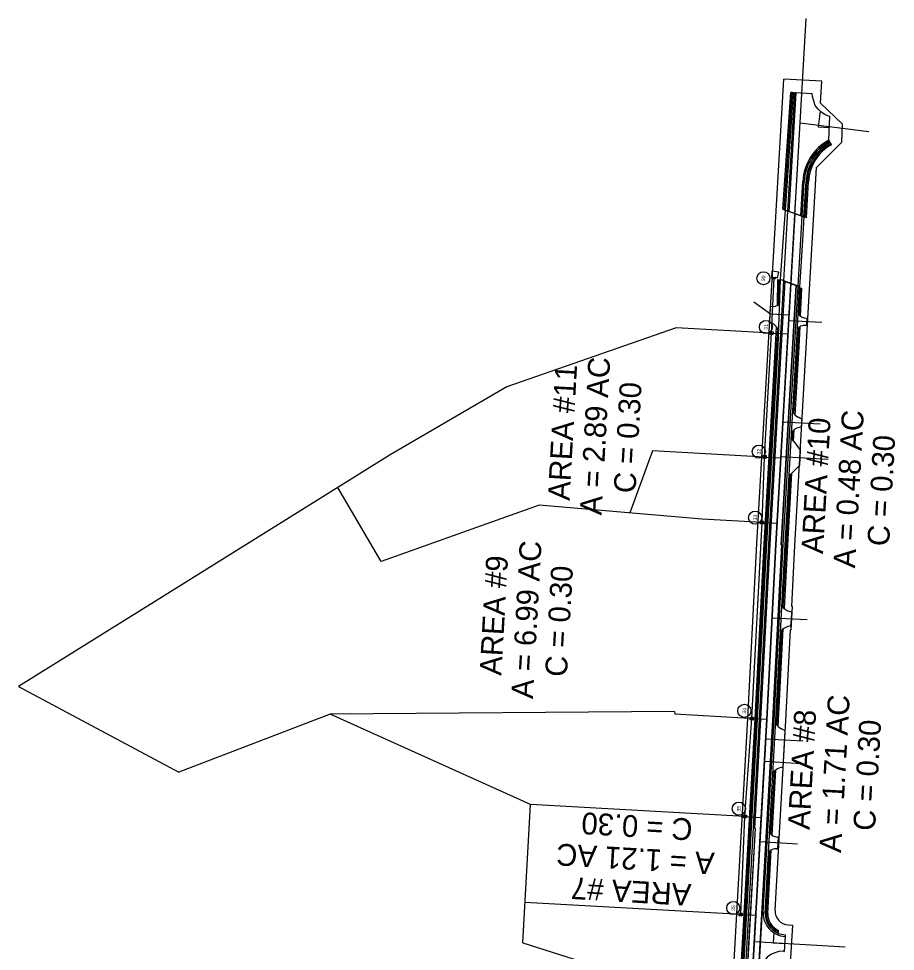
# Model space of a CAD drawing. Extents: x 1972588 to 1974207, y 734965 to 738282.
# Drawn here: x 1972868 to 1974207, y 736857 to 738282 of the extents above; entities that cross this region are included whole.
import ezdxf

# ---------------------------------------------------------------- set-up
doc = ezdxf.new("R2010")
doc.units = 0
for name, color, linetype in [('_CIVIL_CONSTRUCTION', 7, 'Continuous'), ('BR_P_Gen_Ground_Slope', 7, 'Continuous'), ('BR_X_Beam Seat', 7, 'Continuous'), ('BR_X_Bottom of Beam', 7, 'Continuous'), ('BR_X_Gen_Approach_Slab', 7, 'Continuous'), ('BR_X_Pier', 7, 'Continuous'), ('DR_P_GenericNode', 7, 'Continuous'), ('DR_P_Headwall', 7, 'Continuous'), ('DR_P_Storm_Sewer', 7, 'Continuous'), ('DR_X_Cells', 7, 'Continuous'), ('DR_X_GenericNode', 7, 'Continuous'), ('DR_X_Storm_Sewer', 7, 'Continuous'), ('DT_X_Contour_Major', 7, 'Continuous'), ('GE_P_Alignment', 7, 'Continuous'), ('GE_X_Alignment_1000_Cardinal_Points', 7, 'Continuous'), ('GK_Drainage_Nodes', 7, 'Continuous'), ('PF_P_Grade_Line', 7, 'Continuous'), ('RS_Raster1', 7, 'Continuous'), ('SC_ProfileRun2', 7, 'Continuous'), ('SC_ProfileRun4', 7, 'Continuous'), ('SC_Scratch1', 7, 'Continuous')]:
    doc.layers.add(name, color=color, linetype=linetype)

msp = doc.modelspace()

# ---------------------------------------------------------------- linework, layer by layer
at = {"layer": '_CIVIL_CONSTRUCTION'}
for p, q in [((1974014.8, 737818.6), (1974016.3, 737842.9)), ((1974014.8, 737818.6), (1974019.2, 737816)), ((1974071, 737824.5), (1974072.3, 737824.5)), ((1974071.6, 737813.2), (1974072.3, 737824.5)), ((1974071.6, 737813.2), (1974069.3, 737813.3)), ((1974064.2, 737669.6), (1974058.1, 737672.9)), ((1974063.5, 737658.5), (1974059.6, 737657.5)), ((1974063.5, 737658.5), (1974064.2, 737669.6)), ((1974047.7, 737640.6), (1974053.5, 737633.2)), ((1974053.5, 737633.2), (1974061.5, 737622.9)), ((1974061.5, 737622.9), (1974060.3, 737599.1)), ((1974050.7, 737589.6), (1974044.4, 737583.7)), ((1974060.3, 737599.1), (1974050.7, 737589.6)), ((1974048.7, 737374.9), (1974045.1, 737376.1)), ((1974048.2, 737364.6), (1974048.7, 737374.9)), ((1974047.2, 737353.7), (1974048.2, 737364.6)), ((1974038.5, 737194), (1974032.9, 737196.8)), ((1974035.4, 737137.9), (1974038.5, 737194)), ((1974028.4, 737031.3), (1974026, 737031.5)), ((1974027.4, 737013.6), (1974028.4, 737031.3)), ((1974025.5, 737013.7), (1974027.4, 737013.6))]:
    msp.add_line(p, q, dxfattribs=at)
for centre, radius, start, end in [((1974020.1, 737857.4), 15, 255.1663, 311.8101), ((1974071.1, 737839.5), 15, 210.5665, 269.302), ((1974006.4, 737794.5), 25, 27.4365, 59.4001), ((1974068.8, 737798.3), 15, 87.9927, 141.3926), ((1974067.6, 737690.5), 20, 208.4916, 241.7135), ((1974064.6, 737638.1), 20, 104.3781, 144.9149), ((1974051, 737395.2), 20, 208.814, 252.6777), ((1974047.8, 737333.7), 20, 91.8272, 145.2374), ((1974041.6, 737214.8), 20, 208.696, 244.1609), ((1974036.2, 737118), 20, 92.4278, 145.0009), ((1974027.2, 737046.5), 15, 213.6591, 265.4279), ((1974024.5, 736998.7), 15, 86.2628, 139.9193)]:
    msp.add_arc(centre, radius, start, end, dxfattribs=at)
at = {"layer": 'BR_P_Gen_Ground_Slope'}
msp.add_lwpolyline([(1974020.4, 737886.5), (1974020.3, 737884.5), (1974019.3, 737884.6), (1974019.4, 737886.6), (1974023.4, 737886.4), (1974023.3, 737884.4), (1974022.3, 737884.4), (1974022.4, 737886.4)], dxfattribs=at)
at = {"layer": 'BR_X_Beam Seat'}
for p, q in [((1973995.4, 737480.2), (1974036.2, 738189.8)), ((1974094.2, 738186.4), (1974036.2, 738189.8)), ((1974092.2, 738152.8), (1974094.2, 738186.4)), ((1974092.2, 738152.8), (1974126.1, 738121)), ((1974125.1, 738093.3), (1974126.1, 738121)), ((1974086.5, 738054.6), (1974125.1, 738093.3)), ((1974053.3, 737477), (1974086.5, 738054.6)), ((1973981.5, 737212.7), (1973995.4, 737480.2)), ((1974048.4, 737383.8), (1974053.3, 737477)), ((1974047.6, 737348.1), (1974049.4, 737383.8)), ((1974049.4, 737383.8), (1974048.4, 737383.8)), ((1974039.4, 737209.6), (1974046.6, 737348.2)), ((1974046.6, 737348.2), (1974047.6, 737348.1)), ((1973902.9, 735811.8), (1973981.5, 737212.7)), ((1974023.1, 736919.5), (1974039.4, 737209.6)), ((1974042.9, 736897.3), (1974049.4, 736896.9)), ((1974049.4, 736896.9), (1974046.1, 736839))]:
    msp.add_line(p, q, dxfattribs=at)
msp.add_arc((1974044.1, 736918.3), 21, 176.7892, 266.7317, dxfattribs=at)
at = {"layer": 'BR_X_Bottom of Beam'}
msp.add_lwpolyline([(1974023.4, 737886.4), (1974023.8, 737886.9), (1974026.6, 737886), (1974028.8, 737894.7), (1974021.8, 737895.7), (1974018.3, 737896.3), (1974017.8, 737886.7), (1974019.4, 737886.6)], close=True, dxfattribs=at)
at = {"layer": 'BR_X_Gen_Approach_Slab'}
msp.add_circle((1974017.7, 737801.6), 0.5, dxfattribs=at)
at = {"layer": 'BR_X_Pier'}
for p, q in [((1973872, 737809.8), (1973613.2, 737719.5)), ((1974017.7, 737801.6), (1973872, 737809.8)), ((1974017.7, 737801.6), (1974042.8, 737800.2)), ((1974031.9, 737610.8), (1974042.8, 737800.2)), ((1973613.2, 737719.5), (1973435.2, 737615.4)), ((1973435.2, 737615.4), (1973083.5, 737395.9)), ((1973835.8, 737621.8), (1973801.4, 737526.8)), ((1974007, 737612.2), (1973835.8, 737621.8)), ((1974007, 737612.2), (1974031.9, 737610.8)), ((1974026.2, 737511), (1974031.9, 737610.8)), ((1973421.6, 737452.5), (1973355.4, 737565.5)), ((1973662.7, 737538.8), (1973421.6, 737452.5)), ((1973911.8, 737517.3), (1973662.7, 737538.8)), ((1974003.2, 737512.3), (1973911.8, 737517.3)), ((1974003.2, 737512.3), (1974026.2, 737511)), ((1974010.4, 737211.3), (1974026.2, 737511)), ((1973083.5, 737395.9), (1972867.8, 737261.4)), ((1972867.8, 737261.4), (1973112.6, 737130.4)), ((1973343.5, 737219.4), (1973112.6, 737130.4)), ((1973869.3, 737223.5), (1973343.5, 737219.4)), ((1973649.5, 737081.4), (1973343.5, 737219.4)), ((1973869.3, 737223.5), (1973869.9, 737219.2)), ((1974010.4, 737211.3), (1973869.9, 737219.2)), ((1973987.5, 737212.6), (1973999.4, 737212)), ((1974002, 737061.6), (1974010.4, 737211.3)), ((1973637.6, 736869.7), (1973649.5, 737081.4)), ((1973977.1, 737063), (1973649.5, 737081.4)), ((1973977.1, 737063), (1974002, 737061.6)), ((1973993.6, 736911.9), (1974002, 737061.6)), ((1973970.7, 736913.1), (1973641.1, 736931.6)), ((1973970.7, 736913.1), (1973993.6, 736911.9)), ((1973993.6, 736911.9), (1973988.4, 736818.5)), ((1973637.6, 736869.7), (1973783.2, 736823.8))]:
    msp.add_line(p, q, dxfattribs=at)
for centre in [(1974005.2, 737885.3), (1974009, 737810.9), (1973998.3, 737620.4), (1973992.7, 737519.5), (1973976.1, 737224.3), (1973967.7, 737074.8), (1973959.2, 736923.1)]:
    msp.add_circle(centre, 10, dxfattribs=at)
at = {"layer": 'DR_P_GenericNode'}
for points in [[(1974015.4, 737799.6), (1974015.7, 737803.9), (1974020, 737803.7), (1974019.7, 737799.3)], [(1974016.1, 737800.2), (1974016.3, 737803.2), (1974019.3, 737803), (1974019.1, 737800)], [(1974016.5, 737800.5), (1974016.6, 737802.8), (1974018.9, 737802.7), (1974018.8, 737800.4)], [(1974004.7, 737610.2), (1974004.9, 737614.5), (1974009.3, 737614.3), (1974009, 737610)], [(1974005.4, 737610.8), (1974005.6, 737613.8), (1974008.6, 737613.7), (1974008.4, 737610.7)], [(1974005.8, 737611.2), (1974005.9, 737613.5), (1974008.2, 737613.3), (1974008, 737611)], [(1974000.9, 737510.3), (1974001.2, 737514.6), (1974005.5, 737514.3), (1974005.3, 737510)], [(1974001.6, 737510.9), (1974001.8, 737513.9), (1974004.8, 737513.7), (1974004.6, 737510.7)], [(1974002, 737511.2), (1974002.1, 737513.5), (1974004.4, 737513.4), (1974004.3, 737511.1)], [(1973985.2, 737210.5), (1973985.4, 737214.9), (1973989.7, 737214.6), (1973989.5, 737210.3)], [(1973985.9, 737211.2), (1973986, 737214.2), (1973989, 737214), (1973988.9, 737211)], [(1973986.3, 737211.5), (1973986.4, 737213.8), (1973988.7, 737213.7), (1973988.5, 737211.4)], [(1973974.8, 737061), (1973975, 737065.3), (1973979.4, 737065.1), (1973979.1, 737060.7)], [(1973975.5, 737061.6), (1973975.7, 737064.6), (1973978.6, 737064.4), (1973978.5, 737061.4)], [(1973975.9, 737061.9), (1973976, 737064.2), (1973978.3, 737064.1), (1973978.1, 737061.8)], [(1973968.4, 736911.1), (1973968.6, 736915.4), (1973972.9, 736915.2), (1973972.7, 736910.9)], [(1973969.1, 736911.7), (1973969.2, 736914.7), (1973972.2, 736914.6), (1973972.1, 736911.6)], [(1973969.5, 736912.1), (1973969.6, 736914.4), (1973971.9, 736914.2), (1973971.7, 736911.9)]]:
    msp.add_lwpolyline(points, close=True, dxfattribs=at)
at = {"layer": 'DR_P_Headwall'}
for p, q in [((1974016.1, 737830.5), (1973990.7, 737848.7)), ((1974044.5, 737828.9), (1974016.1, 737830.5)), ((1974094.4, 737817.7), (1974044, 737820.5)), ((1974091.8, 737662.5), (1974035.1, 737665.7)), ((1974104, 737608.6), (1974032, 737612.6)), ((1974072, 737363.2), (1974018.5, 737366.2)), ((1974065.4, 737178.1), (1974008.7, 737181.3)), ((1974063.5, 737143.6), (1974006.8, 737146.8)), ((1974057.4, 737020.7), (1973999.9, 737024))]:
    msp.add_line(p, q, dxfattribs=at)
at = {"layer": 'DR_P_Storm_Sewer'}
for p, q in [((1974038.8, 737989.2), (1974051.1, 738168.9)), ((1974051.1, 738168.9), (1974053.1, 738168.8)), ((1974107.1, 738093), (1974106.2, 738094.8)), ((1974067.2, 737979.2), (1974070.3, 738033.1)), ((1974038.8, 737989.2), (1974042.7, 737987.8)), ((1974067.2, 737979.2), (1974064.2, 737980.2)), ((1974027.8, 737782.2), (1974031.4, 737883.3)), ((1974036.5, 737881.4), (1974031.4, 737883.3)), ((1974055.7, 737780.6), (1974060.2, 737872.3)), ((1974060.2, 737872.3), (1974058.1, 737873.1)), ((1974010.3, 737479.4), (1974027.8, 737782.2)), ((1974038.3, 737477.8), (1974055.7, 737780.6)), ((1973996.4, 737211.9), (1974010.3, 737479.3)), ((1974024.4, 737210.4), (1974038.3, 737477.9)), ((1973918.6, 735825.1), (1973996.4, 737211.9)), ((1974007.8, 736914.5), (1974024.4, 737210.4))]:
    msp.add_line(p, q, dxfattribs=at)
for centre, radius, start, end in [((1974142.7, 738029.9), 72.5, 119.3967, 177.4091), ((1974040.1, 736914.4), 32.3, 179.9489, 247.8919)]:
    msp.add_arc(centre, radius, start, end, dxfattribs=at)
at = {"layer": 'DR_X_Cells'}
for p, q in [((1974036.8, 737990), (1974049.1, 738169)), ((1974051.1, 738168.9), (1974049.1, 738169)), ((1974108.1, 738091.3), (1974107.1, 738093)), ((1974069.2, 737978.6), (1974072.3, 738033)), ((1974036.8, 737990), (1974038.8, 737989.2)), ((1974069.2, 737978.6), (1974067.2, 737979.2)), ((1974028.7, 737845.1), (1974029.4, 737882.9)), ((1974029.4, 737882.9), (1974031.4, 737882.3)), ((1974062.1, 737870.4), (1974060.1, 737870.9)), ((1974060.1, 737829.4), (1974062.1, 737870.4)), ((1974025.8, 737782.3), (1974027, 737808.7)), ((1974057.7, 737780.5), (1974059.2, 737809.8)), ((1974008.3, 737479.5), (1974025.8, 737782.3)), ((1974051.8, 737678.2), (1974057.7, 737780.5)), ((1974049.5, 737638.3), (1974050.3, 737652.2)), ((1974040.3, 737477.7), (1974046.5, 737585.7)), ((1973994.4, 737212), (1974008.3, 737479.4)), ((1974035.4, 737382.7), (1974040.3, 737477.8)), ((1974026.4, 737210.3), (1974033.5, 737347.7)), ((1973950.5, 736428.9), (1973994.4, 737212)), ((1974025.9, 737202.4), (1974026.4, 737210.3)), ((1974016.6, 737035.9), (1974022, 737132)), ((1974009.8, 736914.4), (1974015.2, 737010.4)), ((1974027.9, 736884.5), (1974028.1, 736886.6))]:
    msp.add_line(p, q, dxfattribs=at)
for centre, radius, start, end in [((1974142.7, 738029.8), 70.5, 119.3958, 177.4082), ((1974040.1, 736914.4), 30.3, 179.9489, 246.5963)]:
    msp.add_arc(centre, radius, start, end, dxfattribs=at)
at = {"layer": 'DR_X_GenericNode'}
for p, q in [((1974036.5, 737881.4), (1974042.7, 737987.8)), ((1974058.1, 737873.1), (1974064.2, 737980.2))]:
    msp.add_line(p, q, dxfattribs=at)
at = {"layer": 'DR_X_Storm_Sewer'}
for p, q in [((1974088.9, 738116.5), (1974105.9, 738115.7)), ((1974053.4, 737983.8), (1974057.9, 738060.9)), ((1974053.4, 737983.8), (1974024.3, 737478.6)), ((1974024.3, 737478.6), (1974010.4, 737211.2)), ((1974010.4, 737211.2), (1973992.8, 736896.5)), ((1974020, 736869.6), (1974037.7, 736868.6))]:
    msp.add_line(p, q, dxfattribs=at)
at = {"layer": 'DT_X_Contour_Major'}
for p, q in [((1974017.7, 737801.6), (1974021.4, 737886.5)), ((1974007, 737612.2), (1974017.7, 737801.6)), ((1974003.2, 737512.3), (1974007, 737612.2)), ((1973987.5, 737212.6), (1974003.2, 737512.3)), ((1973977.1, 737063), (1973987.5, 737212.6)), ((1973970.7, 736913.1), (1973977.1, 737063))]:
    msp.add_line(p, q, dxfattribs=at)
at = {"layer": 'GE_P_Alignment'}
for p, q in [((1974044.6, 737987.1), (1974055.1, 738168.7)), ((1974055.1, 738168.7), (1974053.1, 738168.8)), ((1974106.2, 738094.8), (1974105.2, 738096.5)), ((1974062.3, 737980.9), (1974065.3, 738033.4)), ((1974015.3, 737479.1), (1974038.5, 737880.6)), ((1974032.3, 737478.2), (1974055.1, 737874.3)), ((1974001.4, 737211.6), (1974015.3, 737479.1)), ((1974019.4, 737210.7), (1974033.3, 737478.1)), ((1974033.3, 737478.1), (1974032.3, 737478.2)), ((1973992, 737044.4), (1974001.4, 737211.6)), ((1973997.7, 736824), (1974019.4, 737210.7)), ((1973976.1, 736742.9), (1973993, 737044.3)), ((1973993, 737044.3), (1973992, 737044.4)), ((1973987.4, 736944.5), (1973986.4, 736944.5))]:
    msp.add_line(p, q, dxfattribs=at)
msp.add_arc((1974142.2, 738029), 77, 118.6908, 176.7032, dxfattribs=at)
at = {"layer": 'GE_X_Alignment_1000_Cardinal_Points'}
for p, q in [((1974021.4, 737886.5), (1974021.4, 737886.5)), ((1974021.4, 737886.5), (1974021.4, 737886.5)), ((1974021.4, 737886.5), (1974021.4, 737886.5)), ((1974021.4, 737886.5), (1974021.4, 737886.5)), ((1974021.4, 737886.5), (1974021.4, 737886.5)), ((1974021.3, 737884.5), (1974021.3, 737884.5)), ((1974015.5, 737801.7), (1974015.5, 737801.7)), ((1974016.2, 737801.7), (1974016.2, 737801.7)), ((1974017.6, 737800.1), (1974017.6, 737800.1)), ((1974017.7, 737801.6), (1974017.7, 737801.6)), ((1974017.7, 737801.6), (1974017.7, 737801.6)), ((1974017.7, 737801.6), (1974017.7, 737801.6)), ((1974017.8, 737803.1), (1974017.8, 737803.1)), ((1974019.2, 737801.5), (1974019.2, 737801.5)), ((1974019.9, 737801.5), (1974019.9, 737801.5)), ((1974004.8, 737612.4), (1974004.8, 737612.4)), ((1974005.5, 737612.3), (1974005.5, 737612.3)), ((1974006.9, 737610.7), (1974006.9, 737610.7)), ((1974007, 737612.2), (1974007, 737612.2)), ((1974007, 737612.2), (1974007, 737612.2)), ((1974007, 737612.2), (1974007, 737612.2)), ((1974007.1, 737613.7), (1974007.1, 737613.7)), ((1974008.5, 737612.2), (1974008.5, 737612.2)), ((1974009.1, 737612.1), (1974009.1, 737612.1)), ((1974001.1, 737512.4), (1974001.1, 737512.4)), ((1974001.7, 737512.4), (1974001.7, 737512.4)), ((1974003.1, 737510.8), (1974003.1, 737510.8)), ((1974003.2, 737512.3), (1974003.2, 737512.3)), ((1974003.2, 737512.3), (1974003.2, 737512.3)), ((1974003.2, 737512.3), (1974003.2, 737512.3)), ((1974003.3, 737513.8), (1974003.3, 737513.8)), ((1974004.7, 737512.2), (1974004.7, 737512.2)), ((1974005.4, 737512.2), (1974005.4, 737512.2)), ((1973985.3, 737212.7), (1973985.3, 737212.7)), ((1973986, 737212.7), (1973986, 737212.7)), ((1973987.4, 737211.1), (1973987.4, 737211.1)), ((1973987.5, 737214.1), (1973987.5, 737214.1)), ((1973987.5, 737212.6), (1973987.5, 737212.6)), ((1973987.5, 737212.6), (1973987.5, 737212.6)), ((1973987.5, 737212.6), (1973987.5, 737212.6)), ((1973989, 737212.5), (1973989, 737212.5)), ((1973989.6, 737212.5), (1973989.6, 737212.5)), ((1973974.9, 737063.1), (1973974.9, 737063.1)), ((1973975.6, 737063.1), (1973975.6, 737063.1)), ((1973977, 737061.5), (1973977, 737061.5)), ((1973977.1, 737063), (1973977.1, 737063)), ((1973977.1, 737063), (1973977.1, 737063)), ((1973977.1, 737063), (1973977.1, 737063)), ((1973977.2, 737064.5), (1973977.2, 737064.5)), ((1973978.6, 737062.9), (1973978.6, 737062.9)), ((1973979.2, 737062.9), (1973979.2, 737062.9)), ((1973968.5, 736913.3), (1973968.5, 736913.3)), ((1973969.2, 736913.2), (1973969.2, 736913.2)), ((1973970.6, 736911.6), (1973970.6, 736911.6)), ((1973970.7, 736914.6), (1973970.7, 736914.6)), ((1973970.7, 736913.1), (1973970.7, 736913.1)), ((1973970.7, 736913.1), (1973970.7, 736913.1)), ((1973970.7, 736913.1), (1973970.7, 736913.1)), ((1973972.2, 736913.1), (1973972.2, 736913.1)), ((1973972.8, 736913), (1973972.8, 736913))]:
    msp.add_line(p, q, dxfattribs=at)
at = {"layer": 'GK_Drainage_Nodes'}
for p, q in [((1974027.8, 736881.9), (1974027.9, 736884.5)), ((1974038.5, 736882.3), (1974038.4, 736879.8))]:
    msp.add_line(p, q, dxfattribs=at)
msp.add_arc((1974039.9, 736914.7), 32.5, 248.478, 267.6185, dxfattribs=at)
at = {"layer": 'PF_P_Grade_Line'}
msp.add_lwpolyline([(1974031.4, 737883.3), (1974036.2, 737955.5), (1974038.8, 737989.2), (1974067.2, 737979.2), (1974065.5, 737952.4), (1974062.7, 737910.9), (1974060.7, 737879.9), (1974060.2, 737872.3), (1974045.3, 737878.1)], close=True, dxfattribs=at)
msp.add_lwpolyline([(1973925.6, 735824.7), (1973947.1, 736206.8), (1973945.1, 736206.9), (1973975.1, 736743), (1973976.1, 736742.9), (1973993, 737044.3), (1973992, 737044.4), (1974001.4, 737211.6), (1974015.3, 737479.1), (1974038.5, 737880.6), (1974055.1, 737874.3), (1974032.3, 737478.2), (1974033.3, 737478.1), (1974019.4, 737210.7), (1973941.6, 735823.8), (1973938.2, 735728.5), (1973919.2, 735729.5), (1973919.9, 735747.5), (1973914.9, 735757.9), (1973912.1, 735760.8), (1973915.4, 735801.8)], dxfattribs=at)
at = {"layer": 'RS_Raster1'}
for p, q in [((1974024.3, 737478.6), (1974070.6, 738282.1)), ((1974166.1, 738109.2), (1974061.4, 738122.2)), ((1974010.4, 737211.2), (1974024.3, 737478.6)), ((1973884.4, 734964.9), (1974010.4, 737211.2)), ((1974130, 736863.3), (1973991.3, 736871.2))]:
    msp.add_line(p, q, dxfattribs=at)
at = {"layer": 'SC_ProfileRun2'}
for p, q in [((1974091.9, 738141), (1974088.9, 738116.5)), ((1974020.9, 736885.3), (1974020, 736869.6))]:
    msp.add_line(p, q, dxfattribs=at)
at = {"layer": 'SC_ProfileRun4'}
for p, q in [((1974034.9, 737990.7), (1974047.1, 738169.2)), ((1974049.1, 738169), (1974047.1, 738169.2)), ((1974109.1, 738089.5), (1974108.1, 738091.3)), ((1974071.2, 737977.9), (1974074.3, 738032.9)), ((1974034.9, 737990.7), (1974036.8, 737990)), ((1974071.2, 737977.9), (1974069.2, 737978.6)), ((1974026.6, 737843.9), (1974027.4, 737883.6)), ((1974027.4, 737883.6), (1974029.4, 737882.9)), ((1974062, 737827.6), (1974064.1, 737869.8)), ((1974064.1, 737869.8), (1974062.1, 737870.4)), ((1974023.8, 737782.4), (1974025.1, 737811.1)), ((1974059.7, 737780.4), (1974061.2, 737811.3)), ((1974006.3, 737479.6), (1974023.8, 737782.4)), ((1974053.7, 737676.1), (1974059.7, 737780.4)), ((1974051.4, 737635.9), (1974052.4, 737654)), ((1974042.3, 737477.6), (1974048.6, 737587.7)), ((1973992.4, 737212.1), (1974006.3, 737479.5)), ((1974037.2, 737380.7), (1974042.3, 737477.7)), ((1974027.9, 737200.3), (1974035.6, 737349.5)), ((1973948.4, 736426.7), (1973992.4, 737212.2)), ((1974018.5, 737034.2), (1974024.1, 737133.9)), ((1974011.8, 736914.2), (1974017.3, 737011.8)), ((1974028.1, 736886.6), (1974028.2, 736888.8))]:
    msp.add_line(p, q, dxfattribs=at)
for centre, radius, start, end in [((1974142.7, 738029.8), 68.5, 119.3744, 177.4082), ((1974040.1, 736914.4), 28.3, 179.9489, 245.1044)]:
    msp.add_arc(centre, radius, start, end, dxfattribs=at)
at = {"layer": 'SC_Scratch1'}
for p, q in [((1974042.7, 737987.8), (1974053.1, 738168.8)), ((1974079.7, 738167.2), (1974053.1, 738168.8)), ((1974080.1, 738163), (1974079.7, 738167.2)), ((1974082.7, 738154.2), (1974080.1, 738163)), ((1974084.3, 738149.4), (1974082.7, 738154.2)), ((1974089, 738143.8), (1974084.3, 738149.4)), ((1974094.2, 738138.8), (1974089, 738143.8)), ((1974099.7, 738135.3), (1974094.2, 738138.8)), ((1974106.5, 738132.4), (1974099.7, 738135.3)), ((1974105.2, 738096.5), (1974106.5, 738132.4)), ((1974106.2, 738094.8), (1974105.2, 738096.5)), ((1974064.2, 737980.2), (1974067.3, 738033.3)), ((1974052.5, 737984.1), (1974042.7, 737987.8)), ((1974064.2, 737980.2), (1974052.5, 737984.1)), ((1974013.3, 737479.2), (1974036.5, 737881.4)), ((1974035.3, 737478), (1974058.1, 737873.1)), ((1974058.1, 737873.1), (1974036.5, 737881.4)), ((1973999.4, 737211.7), (1974013.3, 737479.2)), ((1974021.4, 737210.6), (1974035.3, 737478)), ((1973921.6, 735824.9), (1973999.4, 737211.8)), ((1974004.9, 736916.6), (1974021.4, 737210.5)), ((1974038.4, 736879.8), (1974037.1, 736856.8)), ((1974035.8, 736856.9), (1974037.1, 736856.8))]:
    msp.add_line(p, q, dxfattribs=at)
for centre, radius, start, end in [((1974142.2, 738029), 75, 118.6908, 176.7032), ((1974039.9, 736914.7), 35, 176.7892, 267.5552), ((1974034.7, 736821.9), 35, 87.9533, 176.7892)]:
    msp.add_arc(centre, radius, start, end, dxfattribs=at)

# ---------------------------------------------------------------- texts
at = {"layer": 'BR_X_Pier'}
for s, height, rotation, p in [('30', 5.6, 86.7892, (1974007.7, 737880.7)), ('31', 5.6, 86.7892, (1974011.6, 737806.6)), ('A = 2.89 AC', 33.33, 86.7892, (1973757.9, 737522.8)), ('AREA #11', 33.33, 86.7892, (1973709.1, 737545.1)), ('C = 0.30', 33.33, 86.7892, (1973809.8, 737556.3)), ('A = 0.48 AC', 33.33, 86.7892, (1974145.2, 737441.8)), ('AREA #10', 33.33, 86.7892, (1974096.3, 737463.6)), ('C = 0.30', 33.33, 86.7892, (1974197.1, 737475.3)), ('32', 5.6, 86.7892, (1974000.9, 737615.9)), ('33', 5.6, 86.7892, (1973995.2, 737515.1)), ('A = 6.99 AC', 33.33, 86.7892, (1973653.1, 737242.2)), ('AREA #9', 33.33, 86.7892, (1973605, 737277.7)), ('C = 0.30', 33.33, 86.7892, (1973705, 737275.7)), ('A = 1.71 AC', 33.33, 86.7892, (1974123.7, 737006.9)), ('34', 5.6, 86.7892, (1973978.7, 737219.8)), ('AREA #8', 33.33, 86.7892, (1974075.6, 737042.2)), ('C = 0.30', 33.33, 86.7892, (1974175.6, 737040.4)), ('35', 5.6, 86.7892, (1973970.3, 737070.2)), ('C = 0.30', 33.33, 176.6186, (1973897.9, 737059.4)), ('A = 1.21 AC', 33.33, 176.6186, (1973931.2, 737007.4)), ('AREA #7', 33.33, 176.6186, (1973895.7, 736959.4)), ('36', 5.6, 86.7892, (1973961.8, 736918.5))]:
    msp.add_text(s, height=height, rotation=rotation, dxfattribs=at).set_placement(p)

doc.saveas('drawing.dxf')
